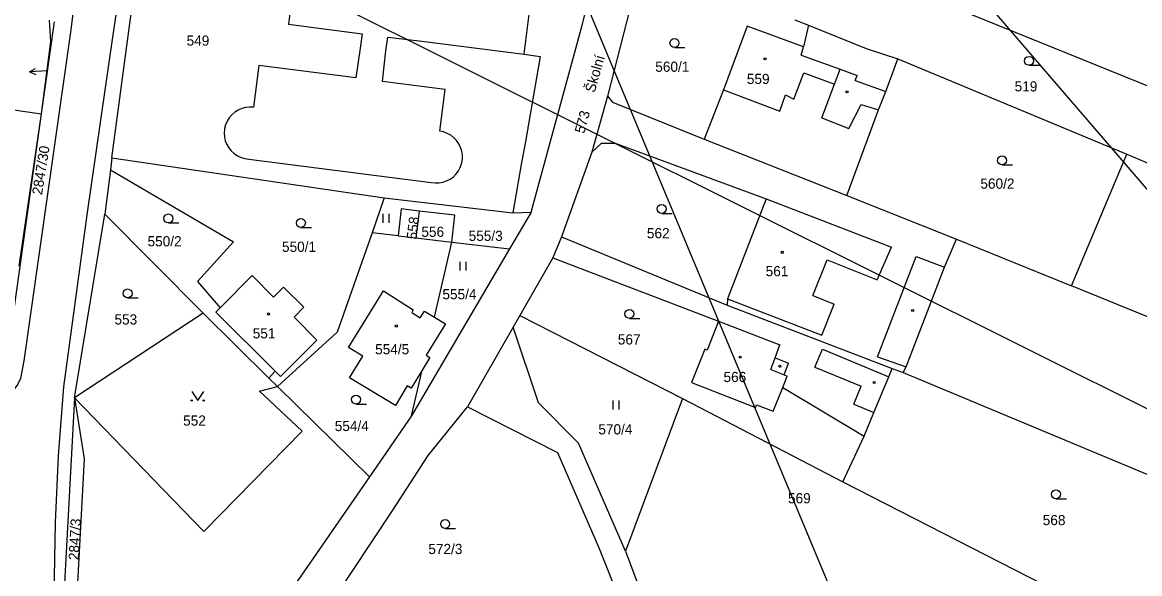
# Model space of a CAD drawing. Extents: x -558358 to -557517, y -1073786 to -1073189.
# Drawn here: x -558184.5 to -557998, y -1073651.5 to -1073559.5 of the extents above; entities that cross this region are included whole.
import ezdxf

# ---------------------------------------------------------------- set-up
doc = ezdxf.new("R2010")
doc.units = 0
for name, color, linetype in [('Hranice parcel', 7, 'Continuous'), ('Parcelní čísla', 7, 'Continuous'), ('Pop  PČ popisy', 7, 'Continuous'), ('Vnitřní kresba', 7, 'Continuous'), ('Vrstva 28', 7, 'Continuous'), ('Značky budov', 7, 'Continuous'), ('Značky kultur', 7, 'Continuous')]:
    doc.layers.add(name, color=color, linetype=linetype)

msp = doc.modelspace()

# ---------------------------------------------------------------- linework, layer by layer
at = {"layer": 'Hranice parcel'}
for p, q in [((-558174.43, -1073545.49), (-558176.44, -1073560.75)), ((-558080.96, -1073549.01), (-558086.83, -1073571.83)), ((-558181.3, -1073574.78), (-558179.14, -1073559.41)), ((-558055.56, -1073559.09), (-558053.26, -1073559.97)), ((-558038.36, -1073565.55), (-558000.16, -1073581.51)), ((-558219.67, -1073569.09), (-558181.3, -1073574.78)), ((-558086.83, -1073571.83), (-558089.47, -1073581.15)), ((-558187.72, -1073620.52), (-558181.3, -1073574.78)), ((-558185.06, -1073600.21), (-558181.3, -1073574.78)), ((-558070.72, -1073578.99), (-558046.87, -1073588.38)), ((-558089.47, -1073581.15), (-558094.5, -1073595.31)), ((-558009.36, -1073603.49), (-558000.16, -1073581.51)), ((-558000.16, -1073581.51), (-557977.41, -1073591.02)), ((-558169.56, -1073582.12), (-558169.81, -1073584.08)), ((-558169.56, -1073582.12), (-558124.1, -1073588.8)), ((-558146.72, -1073582.31), (-558116.26, -1073586.22)), ((-558169.81, -1073584.08), (-558170.74, -1073591.52)), ((-558124.1, -1073588.8), (-558126.13, -1073594.62)), ((-558124.1, -1073588.8), (-558102.62, -1073591.27)), ((-558046.87, -1073588.38), (-558028.58, -1073595.68)), ((-558118.29, -1073590.98), (-558118.81, -1073595.47)), ((-558099.6, -1073591.18), (-558103.17, -1073597.28)), ((-558102.62, -1073591.27), (-558099.6, -1073591.18)), ((-558175.82, -1073622.18), (-558170.74, -1073591.52)), ((-558154.32, -1073608.02), (-558170.74, -1073591.52)), ((-558121.8, -1073595.12), (-558126.13, -1073594.62)), ((-558121.8, -1073595.12), (-558118.81, -1073595.47)), ((-558118.81, -1073595.47), (-558112.83, -1073596.16)), ((-558115.73, -1073608.72), (-558112.83, -1073596.16)), ((-558112.83, -1073596.16), (-558103.17, -1073597.28)), ((-558094.5, -1073595.31), (-558095.93, -1073598.78)), ((-558094.5, -1073595.31), (-558066.88, -1073606.68)), ((-558028.58, -1073595.68), (-558009.36, -1073603.49)), ((-558103.17, -1073597.28), (-558119.53, -1073625.2)), ((-558095.93, -1073598.78), (-558101.44, -1073608.4)), ((-558155.28, -1073602.76), (-558151.5, -1073607.15)), ((-557981.3, -1073614.89), (-558009.36, -1073603.49)), ((-558154.32, -1073608.02), (-558175.82, -1073622.18)), ((-558143.35, -1073618.87), (-558154.32, -1073608.02)), ((-558066.88, -1073606.68), (-558039.3, -1073617.26)), ((-558101.44, -1073608.4), (-558102.56, -1073610.37)), ((-558101.44, -1073608.4), (-558074.34, -1073622.3)), ((-558102.56, -1073610.37), (-558110.18, -1073623.69)), ((-558039.3, -1073617.26), (-558037.5, -1073617.95)), ((-558142.28, -1073617.72), (-558143.35, -1073618.87)), ((-558141.92, -1073620.28), (-558143.35, -1073618.87)), ((-558119.53, -1073625.2), (-558117.76, -1073617.53)), ((-558126.57, -1073635.37), (-558141.92, -1073620.28)), ((-558074.34, -1073622.3), (-558083.83, -1073647.78)), ((-558074.34, -1073622.3), (-558047.53, -1073636.2)), ((-558119.53, -1073625.2), (-558126.57, -1073635.37)), ((-558047.53, -1073636.2), (-558043.97, -1073628.57)), ((-558083.83, -1073647.78), (-558091.67, -1073629.76)), ((-558126.57, -1073635.37), (-558152.59, -1073672.96)), ((-558047.53, -1073636.2), (-557987.38, -1073666.93)), ((-558083.83, -1073647.78), (-558081.75, -1073653.27))]:
    msp.add_line(p, q, dxfattribs=at)
for points in [[(-558086.19, -1073392.25), (-558100.56, -1073410.01), (-558117.51, -1073431.08), (-558131.78, -1073449.27), (-558138.48, -1073457.68), (-558143.38, -1073464.02), (-558146.99, -1073468.89), (-558150.46, -1073473.83), (-558152.02, -1073476.41), (-558154.26, -1073480.97), (-558156.46, -1073486.6), (-558158.91, -1073494.31), (-558160.3, -1073500.48), (-558162.16, -1073510.4), (-558165.76, -1073536.46), (-558169.94, -1073565.43), (-558173.74, -1073591.61), (-558177.66, -1073620.33), (-558178.51, -1073631.87), (-558179.02, -1073643), (-558179.24, -1073655.12), (-558179.45, -1073666.94), (-558179.49, -1073675.4)], [(-558169.56, -1073582.12), (-558166.59, -1073559.69), (-558162.5, -1073531.6)], [(-558137.04, -1073535.13), (-558138.34, -1073545.94), (-558140.1, -1073559.78), (-558127.81, -1073561.38), (-558128.13, -1073563.82), (-558128.85, -1073568.77)], [(-558099.6, -1073591.18), (-558091.09, -1073560.2), (-558086.54, -1073542.34)], [(-557977.41, -1073591.02), (-557981.5, -1073577.12), (-557984.25, -1073575.17), (-558047.33, -1073549.53)], [(-558181.3, -1073574.78), (-558179.75, -1073562.68), (-558179.99, -1073559.12)], [(-558176.44, -1073560.75), (-558184.28, -1073616.01), (-558184.84, -1073618.94), (-558185.24, -1073619.89), (-558185.86, -1073620.72), (-558186.64, -1073621.38)], [(-558053.26, -1073559.97), (-558054.09, -1073563.56), (-558063.5, -1073560.11), (-558067.45, -1073570.76), (-558070.72, -1073578.99)], [(-558053.26, -1073559.97), (-558043.68, -1073563.84), (-558038.36, -1073565.55)], [(-558124.4, -1073569.34), (-558123.84, -1073564.23), (-558123.49, -1073561.94), (-558118.73, -1073562.49), (-558100.77, -1073564.79), (-558098.05, -1073565.18), (-558100.59, -1073579.72), (-558101.17, -1073582.9), (-558102.62, -1073591.27)], [(-558128.85, -1073568.77), (-558145.05, -1073566.7), (-558145.94, -1073573.66)], [(-558046.87, -1073588.38), (-558041.59, -1073574.1), (-558040.35, -1073571.05), (-558038.36, -1073565.55)], [(-558114.83, -1073577.66), (-558113.93, -1073570.69), (-558124.4, -1073569.34)], [(-558086.83, -1073571.83), (-558085.98, -1073572.82), (-558070.72, -1073578.99)], [(-558145.94, -1073573.66), (-558146.6, -1073573.63), (-558147.25, -1073573.7), (-558147.89, -1073573.86), (-558148.5, -1073574.12), (-558149.06, -1073574.47), (-558149.56, -1073574.9), (-558149.98, -1073575.4), (-558150.33, -1073575.96), (-558150.59, -1073576.57), (-558150.76, -1073577.21), (-558150.78, -1073577.3), (-558150.83, -1073577.96), (-558150.78, -1073578.62), (-558150.63, -1073579.26), (-558150.39, -1073579.87), (-558150.06, -1073580.44), (-558149.64, -1073580.95), (-558149.15, -1073581.4), (-558148.6, -1073581.76), (-558148.01, -1073582.04), (-558147.37, -1073582.22), (-558146.72, -1073582.31)], [(-558116.26, -1073586.22), (-558115.61, -1073586.3), (-558114.95, -1073586.29), (-558114.3, -1073586.17), (-558113.68, -1073585.96), (-558113.09, -1073585.66), (-558112.56, -1073585.27), (-558112.09, -1073584.8), (-558111.7, -1073584.27), (-558111.4, -1073583.69), (-558111.18, -1073583.06), (-558111.15, -1073582.95), (-558111.05, -1073582.3), (-558111.05, -1073581.64), (-558111.15, -1073580.99), (-558111.35, -1073580.36), (-558111.64, -1073579.77), (-558112.02, -1073579.22), (-558112.47, -1073578.75), (-558112.99, -1073578.34), (-558113.57, -1073578.02), (-558114.19, -1073577.79), (-558114.83, -1073577.66)], [(-558089.47, -1073581.15), (-558087.83, -1073579.66), (-558085.58, -1073579.68), (-558060.36, -1073588.97), (-558066.81, -1073605.67), (-558066.88, -1073606.68)], [(-558169.81, -1073584.08), (-558149.27, -1073596.11), (-558155.28, -1073602.76)], [(-558118.29, -1073590.98), (-558121.28, -1073590.64), (-558121.8, -1073595.12)], [(-558112.83, -1073596.16), (-558112.31, -1073591.67), (-558118.29, -1073590.98)], [(-558126.13, -1073594.62), (-558131.94, -1073611.23), (-558141.92, -1073620.28)], [(-558037.5, -1073617.95), (-558036.99, -1073617), (-558030.56, -1073600.34), (-558028.58, -1073595.68)], [(-558095.93, -1073598.78), (-558068.28, -1073609.38), (-558070.18, -1073614.23), (-558070.6, -1073614.06), (-558072.8, -1073619.63), (-558062.12, -1073623.77), (-558061.94, -1073623.36), (-558059.17, -1073624.37), (-558057.59, -1073620.43), (-558043.97, -1073628.57)], [(-558142.28, -1073617.72), (-558141.4, -1073618.59), (-558135.35, -1073612.55), (-558139.15, -1073608.7), (-558137.51, -1073607.05), (-558140.91, -1073603.7), (-558142.57, -1073605.38), (-558146.16, -1073601.75), (-558151.5, -1073607.15)], [(-558117.76, -1073617.53), (-558119.58, -1073620.56), (-558120.26, -1073620.18), (-558122.2, -1073623.43), (-558129.88, -1073618.85), (-558127.67, -1073615.2), (-558130.05, -1073613.78), (-558124.22, -1073604.32), (-558119.25, -1073607.46), (-558119.52, -1073607.94), (-558118.12, -1073608.84), (-558117.4, -1073607.72), (-558115.73, -1073608.72)], [(-558151.5, -1073607.15), (-558152.22, -1073607.87), (-558142.28, -1073617.72)], [(-558115.73, -1073608.72), (-558113.89, -1073609.83), (-558117.1, -1073615.05), (-558116.51, -1073615.45), (-558117.76, -1073617.53)], [(-558091.67, -1073629.76), (-558098.34, -1073623.01), (-558102.56, -1073610.37)], [(-558043.97, -1073628.57), (-558042.35, -1073624.63), (-558039.87, -1073618.65), (-558039.3, -1073617.26)], [(-558037.5, -1073617.95), (-557968.93, -1073646.57), (-557957.49, -1073653.98)], [(-558175.82, -1073622.18), (-558161, -1073637.48), (-558154.2, -1073644.46), (-558137.82, -1073627.75), (-558144.92, -1073621.06), (-558141.92, -1073620.28)], [(-558175.82, -1073622.18), (-558177.63, -1073656.22), (-558176.05, -1073666.5)], [(-558175.82, -1073622.18), (-558174.18, -1073632.38), (-558176.05, -1073666.5)], [(-558143.16, -1073671.79), (-558122.68, -1073640.91), (-558116.74, -1073631.82), (-558110.18, -1073623.69)], [(-558110.18, -1073623.69), (-558095.16, -1073631.27), (-558088.2, -1073647.35), (-558084.61, -1073656.37)]]:
    msp.add_lwpolyline(points, dxfattribs=at)
at = {"layer": 'Pop  PČ popisy'}
for p, q in [((-558183.31, -1073567.74), (-558182.33, -1073567.19)), ((-558180.31, -1073567.58), (-558183.31, -1073567.74)), ((-558183.31, -1073567.74), (-558182.28, -1073568.19))]:
    msp.add_line(p, q, dxfattribs=at)
at = {"layer": 'Vnitřní kresba'}
for p, q in [((-558100.77, -1073564.79), (-558099.8, -1073557.24)), ((-558054.51, -1073564.95), (-558054.09, -1073563.56)), ((-558054.51, -1073564.95), (-558048, -1073567.3)), ((-558055.72, -1073572.3), (-558054.04, -1073567.93)), ((-558054.04, -1073567.93), (-558048.94, -1073569.79)), ((-558048.94, -1073569.79), (-558048, -1073567.3)), ((-558048, -1073567.3), (-558045.17, -1073568.34)), ((-558045.48, -1073569.18), (-558045.17, -1073568.34)), ((-558067.45, -1073570.76), (-558058.09, -1073574.3)), ((-558051.08, -1073575.44), (-558048.94, -1073569.79)), ((-558045.48, -1073569.18), (-558040.35, -1073571.05)), ((-558058.09, -1073574.3), (-558057.1, -1073571.59)), ((-558057.1, -1073571.59), (-558055.72, -1073572.3)), ((-558046.52, -1073577.2), (-558044.47, -1073573.2)), ((-558044.47, -1073573.2), (-558041.59, -1073574.1)), ((-558051.08, -1073575.44), (-558046.52, -1073577.2)), ((-558060.36, -1073588.97), (-558039.44, -1073597)), ((-558041.81, -1073602.48), (-558039.44, -1073597)), ((-558041.75, -1073615.33), (-558035.32, -1073598.58)), ((-558035.32, -1073598.58), (-558030.56, -1073600.34)), ((-558052.58, -1073605.08), (-558050.15, -1073599.12)), ((-558050.15, -1073599.12), (-558041.81, -1073602.48)), ((-558066.81, -1073605.67), (-558051.04, -1073611.69)), ((-558052.58, -1073605.08), (-558049.01, -1073606.53)), ((-558051.04, -1073611.69), (-558049.01, -1073606.53)), ((-558068.28, -1073609.38), (-558058.04, -1073613.34)), ((-558058.85, -1073615.47), (-558058.04, -1073613.34)), ((-558059.56, -1073617.45), (-558058.85, -1073615.47)), ((-558058.85, -1073615.47), (-558056.6, -1073616.37)), ((-558052.22, -1073617.07), (-558050.97, -1073614.06)), ((-558050.97, -1073614.06), (-558039.87, -1073618.65)), ((-558041.75, -1073615.33), (-558036.99, -1073617)), ((-558057.32, -1073618.35), (-558056.6, -1073616.37)), ((-558052.22, -1073617.07), (-558044.49, -1073620.2)), ((-558059.56, -1073617.45), (-558057.32, -1073618.35)), ((-558057.59, -1073620.43), (-558056.83, -1073618.55)), ((-558057.32, -1073618.35), (-558056.83, -1073618.55)), ((-558045.71, -1073623.2), (-558044.49, -1073620.2)), ((-558045.71, -1073623.2), (-558042.35, -1073624.63))]:
    msp.add_line(p, q, dxfattribs=at)
at = {"layer": 'Vrstva 28'}
for p, q in [((-558150.5, -1073408.33), (-557941.76, -1073651.48)), ((-558150.16, -1073413.05), (-558044.9, -1073665.43)), ((-558220.14, -1073512.46), (-557941.76, -1073651.48))]:
    msp.add_line(p, q, dxfattribs=at)
at = {"layer": 'Značky budov'}
for centre in [(-558060.53, -1073565.58), (-558046.85, -1073571.1), (-558057.66, -1073597.88), (-558143.42, -1073608.17), (-558035.89, -1073607.59), (-558122.08, -1073610.17), (-558064.7, -1073615.39), (-558058.07, -1073616.9), (-558042.33, -1073619.61)]:
    msp.add_circle(centre, 0.175, dxfattribs=at)
at = {"layer": 'Značky kultur'}
for p, q in [((-558075.65, -1073563.69), (-558073.9, -1073563.69)), ((-558016.47, -1073566.66), (-558014.72, -1073566.66)), ((-558020.96, -1073583.29), (-558019.21, -1073583.29)), ((-558160.14, -1073592.98), (-558158.39, -1073592.98)), ((-558124.27, -1073592.93), (-558124.27, -1073591.43)), ((-558123.27, -1073592.93), (-558123.27, -1073591.43)), ((-558077.78, -1073591.38), (-558076.03, -1073591.38)), ((-558138.02, -1073593.72), (-558136.27, -1073593.72)), ((-558111.42, -1073600.94), (-558111.42, -1073599.44)), ((-558110.42, -1073600.94), (-558110.42, -1073599.44)), ((-558166.95, -1073605.5), (-558165.2, -1073605.5)), ((-558083.17, -1073608.9), (-558081.42, -1073608.9)), ((-558085.87, -1073624.09), (-558085.87, -1073622.59)), ((-558084.87, -1073624.09), (-558084.87, -1073622.59)), ((-558128.81, -1073623.2), (-558127.06, -1073623.2)), ((-558011.98, -1073639.01), (-558010.23, -1073639.01)), ((-558113.93, -1073643.96), (-558112.18, -1073643.96))]:
    msp.add_line(p, q, dxfattribs=at)
msp.add_lwpolyline([(-558156.24, -1073621.11), (-558155.24, -1073622.61), (-558154.24, -1073621.11)], dxfattribs=at)
for centre, radius in [((-558075.65, -1073562.94), 0.75), ((-558016.47, -1073565.91), 0.75), ((-558020.96, -1073582.54), 0.75), ((-558077.78, -1073590.63), 0.75), ((-558160.14, -1073592.23), 0.75), ((-558138.02, -1073592.97), 0.75), ((-558166.95, -1073604.75), 0.75), ((-558083.17, -1073608.15), 0.75), ((-558156.24, -1073622.61), 0.1), ((-558154.24, -1073622.61), 0.1), ((-558128.81, -1073622.45), 0.75), ((-558011.98, -1073638.26), 0.75), ((-558113.93, -1073643.21), 0.75)]:
    msp.add_circle(centre, radius, dxfattribs=at)

# ---------------------------------------------------------------- texts
at = {"layer": 'Parcelní čísla'}
for s, p in [('549', (-558157.09, -1073563.38)), ('560/1', (-558078.86, -1073567.74)), ('559', (-558063.57, -1073569.78)), ('519', (-558018.87, -1073571.02)), ('560/2', (-558024.59, -1073587.26)), ('556', (-558117.9, -1073595.3)), ('555/3', (-558110.01, -1073595.97)), ('562', (-558080.26, -1073595.54)), ('550/2', (-558163.61, -1073596.88)), ('550/1', (-558141.17, -1073597.8)), ('561', (-558060.43, -1073601.87)), ('555/4', (-558114.39, -1073605.72)), ('553', (-558169.13, -1073609.93)), ('551', (-558146.05, -1073612.25)), ('567', (-558085.11, -1073613.27)), ('554/5', (-558125.62, -1073614.91)), ('566', (-558067.47, -1073619.54)), ('552', (-558157.67, -1073626.81)), ('554/4', (-558132.36, -1073627.72)), ('570/4', (-558088.36, -1073628.28)), ('569', (-558056.7, -1073639.78)), ('568', (-558014.18, -1073643.43)), ('572/3', (-558116.74, -1073648.25))]:
    msp.add_text(s, height=1.7, dxfattribs=at).set_placement(p)
for s, rotation, p in [('573', 75, (-558090.71, -1073578.15)), ('2847/30', 81, (-558181.23, -1073588.36)), ('558', 83, (-558118.7, -1073595.8)), ('2847/3', 87, (-558175.1, -1073649.31))]:
    msp.add_text(s, height=1.7, rotation=rotation, dxfattribs=at).set_placement(p)
at = {"layer": 'Pop  PČ popisy'}
msp.add_text('Školní', height=1.7, rotation=74, dxfattribs=at).set_placement((-558088.99, -1073571.32))

doc.saveas('drawing.dxf')
